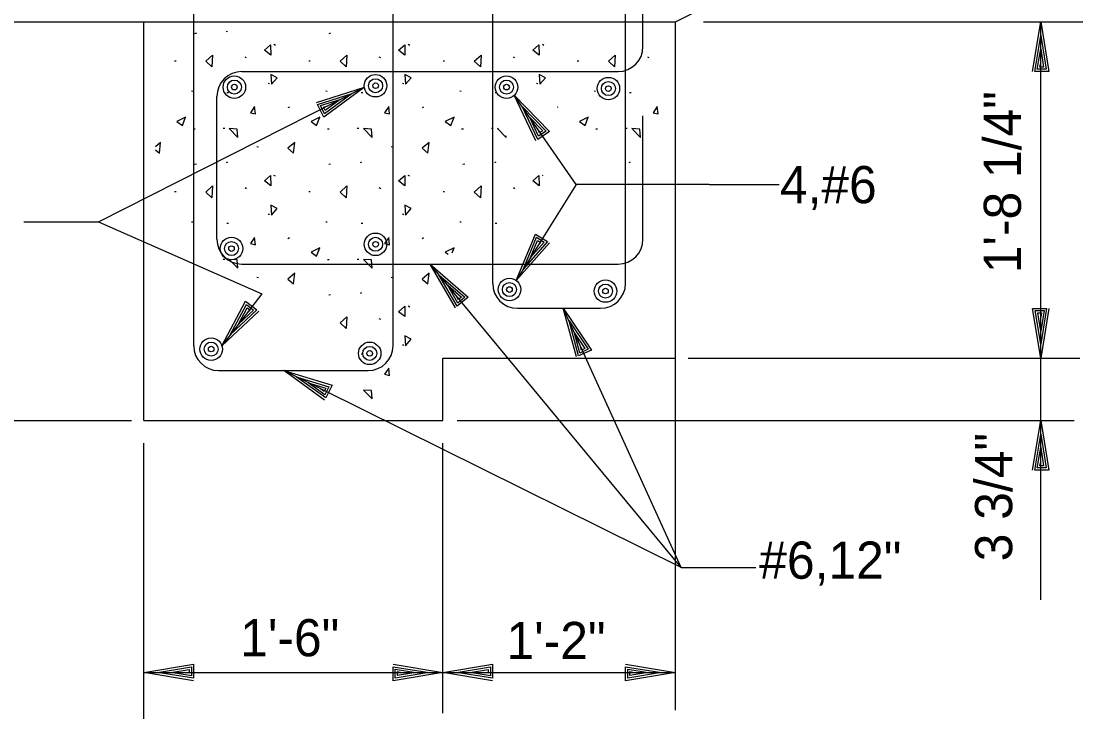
# Model space of a CAD drawing. Extents: x -48 to 108, y -5 to 100.
# Drawn here: x 89 to 99.6, y 26.59 to 33.58 of the extents above; entities that cross this region are included whole.
import ezdxf

# ---------------------------------------------------------------- set-up
doc = ezdxf.new("R2010")
doc.units = 0
for name, color, linetype in [('Level 2', 7, 'Continuous'), ('Level 25', 7, 'Continuous'), ('Level 44', 7, 'Continuous'), ('Level 50', 7, 'Continuous')]:
    doc.layers.add(name, color=color, linetype=linetype)

msp = doc.modelspace()

# ---------------------------------------------------------------- linework, layer by layer
at = {"layer": 'Level 2'}
for p, q in [((95.061, 30.954), (95.061, 36.712)), ((92.728, 30.329), (92.728, 36.585)), ((90.728, 30.329), (90.728, 34.809)), ((93.728, 30.954), (93.728, 34.809)), ((95.236, 33.329), (95.236, 34.852)), ((83.634, 33.579), (95.561, 33.579)), ((90.228, 29.579), (90.228, 33.579)), ((95.561, 30.204), (95.561, 33.579)), ((95.843, 33.579), (99.65, 33.579)), ((99.227, 30.204), (99.227, 33.579)), ((91.211, 33.079), (94.986, 33.079)), ((89.772, 31.573), (92.441, 32.921)), ((90.961, 31.397), (90.961, 32.829)), ((94.567, 31.947), (93.945, 32.842)), ((95.236, 31.397), (95.236, 32.636)), ((94.567, 31.947), (93.962, 30.983)), ((95.901, 31.947), (94.567, 31.947)), ((95.901, 31.947), (96.601, 31.947)), ((89.024, 31.573), (89.772, 31.573)), ((89.772, 31.573), (91.411, 30.849)), ((91.211, 31.147), (94.986, 31.147)), ((95.619, 28.104), (93.1, 31.147)), ((91.411, 30.849), (91.01, 30.329)), ((93.978, 30.704), (94.811, 30.704)), ((95.619, 28.104), (94.436, 30.704)), ((93.228, 29.579), (93.228, 30.204)), ((93.228, 30.204), (95.561, 30.204)), ((95.561, 26.671), (95.561, 30.204)), ((95.688, 30.204), (99.621, 30.204)), ((99.227, 29.579), (99.227, 30.204)), ((90.978, 30.079), (92.478, 30.079)), ((95.619, 28.104), (91.632, 30.079)), ((85.957, 29.579), (90.105, 29.579)), ((90.228, 29.579), (93.228, 29.579)), ((93.371, 29.579), (99.563, 29.579)), ((99.227, 27.779), (99.227, 29.579)), ((90.228, 26.585), (90.228, 29.351)), ((93.228, 26.642), (93.228, 29.351)), ((95.619, 28.104), (96.367, 28.104)), ((90.228, 27.051), (93.228, 27.051)), ((93.228, 27.051), (95.561, 27.051))]:
    msp.add_line(p, q, dxfattribs=at)
for centre, start, end in [((94.986, 33.329), 270, 0), ((91.211, 32.829), 90, 180), ((91.211, 31.397), 180, 270), ((94.986, 31.397), 270, 0), ((93.978, 30.954), 180, 270), ((94.811, 30.954), 270, 0), ((90.978, 30.329), 180, 270), ((92.478, 30.329), 270, 0)]:
    msp.add_arc(centre, 0.25, start, end, dxfattribs=at)
at = {"layer": 'Level 25'}
msp.add_line((95.561, 33.579), (100.142, 35.869), dxfattribs=at)
at = {"layer": 'Level 44'}
for p, q in [((90.755, 33.463), (90.737, 33.458)), ((91.066, 33.481), (91.053, 33.476)), ((92.102, 33.463), (92.084, 33.458)), ((91.548, 33.34), (91.533, 33.349)), ((92.895, 33.34), (92.88, 33.349)), ((94.242, 33.34), (94.227, 33.349)), ((91.258, 33.216), (91.244, 33.222)), ((92.605, 33.216), (92.59, 33.222)), ((93.951, 33.216), (93.937, 33.222)), ((95.298, 33.216), (95.284, 33.222)), ((90.551, 33.184), (90.536, 33.182)), ((91.898, 33.184), (91.883, 33.182)), ((93.244, 33.184), (93.23, 33.182)), ((94.591, 33.184), (94.576, 33.182)), ((90.719, 32.879), (90.706, 32.881)), ((91.488, 32.957), (91.475, 32.958)), ((92.066, 32.879), (92.053, 32.881)), ((92.835, 32.957), (92.822, 32.958)), ((93.413, 32.879), (93.399, 32.881)), ((94.182, 32.957), (94.168, 32.958)), ((94.759, 32.879), (94.746, 32.881)), ((91.078, 32.867), (91.06, 32.867)), ((92.425, 32.867), (92.407, 32.867)), ((93.771, 32.867), (93.753, 32.867)), ((95.118, 32.867), (95.1, 32.867)), ((91.689, 32.722), (91.673, 32.714)), ((93.035, 32.722), (93.019, 32.714)), ((94.382, 32.722), (94.374, 32.718)), ((90.741, 32.5), (90.723, 32.5)), ((91.039, 32.507), (91.022, 32.507)), ((92.087, 32.5), (92.069, 32.5)), ((92.386, 32.507), (92.369, 32.507)), ((93.434, 32.5), (93.416, 32.5)), ((93.733, 32.507), (93.716, 32.507)), ((94.781, 32.5), (94.763, 32.5)), ((95.079, 32.507), (95.062, 32.507)), ((91.379, 32.32), (91.361, 32.323)), ((92.725, 32.32), (92.708, 32.323)), ((90.755, 32.151), (90.737, 32.146)), ((91.066, 32.169), (91.053, 32.164)), ((92.102, 32.151), (92.084, 32.146)), ((92.412, 32.169), (92.399, 32.164)), ((93.448, 32.151), (93.43, 32.146)), ((93.759, 32.169), (93.746, 32.164)), ((95.106, 32.169), (95.093, 32.164)), ((91.548, 32.028), (91.533, 32.037)), ((92.895, 32.028), (92.88, 32.037)), ((94.233, 32.033), (94.227, 32.037)), ((90.551, 31.872), (90.536, 31.871)), ((91.258, 31.904), (91.244, 31.911)), ((91.898, 31.872), (91.883, 31.871)), ((92.605, 31.904), (92.59, 31.911)), ((93.244, 31.872), (93.23, 31.871)), ((93.951, 31.904), (93.937, 31.911)), ((91.488, 31.645), (91.475, 31.646)), ((92.835, 31.645), (92.822, 31.646)), ((90.719, 31.567), (90.706, 31.569)), ((91.078, 31.556), (91.06, 31.556)), ((92.066, 31.567), (92.053, 31.569)), ((92.425, 31.556), (92.407, 31.556)), ((93.413, 31.567), (93.399, 31.569)), ((93.771, 31.556), (93.753, 31.556)), ((91.689, 31.41), (91.673, 31.402)), ((93.035, 31.41), (93.019, 31.402)), ((91.039, 31.195), (91.022, 31.195)), ((92.087, 31.189), (92.069, 31.189)), ((92.386, 31.195), (92.369, 31.195)), ((91.379, 31.009), (91.361, 31.012)), ((92.725, 31.009), (92.708, 31.012)), ((92.412, 30.858), (92.399, 30.853)), ((92.102, 30.84), (92.084, 30.835)), ((92.895, 30.716), (92.88, 30.725)), ((92.605, 30.592), (92.59, 30.599)), ((92.835, 30.333), (92.822, 30.334)), ((92.425, 30.244), (92.407, 30.244))]:
    msp.add_line(p, q, dxfattribs=at)
for points in [[(91.501, 33.245), (91.437, 33.294), (91.498, 33.348)], [(92.848, 33.245), (92.784, 33.294), (92.845, 33.348)], [(94.194, 33.245), (94.13, 33.294), (94.192, 33.348)], [(90.911, 33.125), (90.85, 33.182), (90.918, 33.243)], [(92.258, 33.125), (92.196, 33.182), (92.265, 33.243)], [(93.605, 33.125), (93.543, 33.182), (93.611, 33.243)], [(94.951, 33.125), (94.89, 33.182), (94.958, 33.243)], [(91.508, 32.952), (91.565, 33.016), (91.501, 33.05)], [(92.854, 32.952), (92.911, 33.016), (92.848, 33.05)], [(94.201, 32.952), (94.258, 33.016), (94.194, 33.05)], [(91.347, 32.654), (91.338, 32.727), (91.297, 32.666)], [(92.694, 32.654), (92.685, 32.727), (92.644, 32.666)], [(95.387, 32.654), (95.378, 32.727), (95.337, 32.666)], [(90.615, 32.539), (90.646, 32.621), (90.558, 32.578)], [(91.961, 32.539), (91.993, 32.621), (91.905, 32.578)], [(93.308, 32.539), (93.34, 32.621), (93.251, 32.578)], [(94.655, 32.539), (94.686, 32.621), (94.598, 32.578)], [(91.164, 32.502), (91.084, 32.507), (91.171, 32.418)], [(92.511, 32.502), (92.431, 32.507), (92.518, 32.418)], [(95.204, 32.502), (95.124, 32.507), (95.211, 32.418)], [(91.743, 32.368), (91.674, 32.309), (91.731, 32.261)], [(93.089, 32.368), (93.021, 32.309), (93.078, 32.261)], [(91.501, 31.934), (91.437, 31.982), (91.498, 32.036)], [(92.848, 31.934), (92.784, 31.982), (92.845, 32.036)], [(94.194, 31.934), (94.13, 31.982), (94.192, 32.036)], [(90.911, 31.813), (90.85, 31.87), (90.918, 31.931)], [(92.258, 31.813), (92.196, 31.87), (92.265, 31.931)], [(93.605, 31.813), (93.543, 31.87), (93.611, 31.931)], [(91.508, 31.64), (91.565, 31.704), (91.501, 31.738)], [(92.854, 31.64), (92.911, 31.704), (92.848, 31.738)], [(91.347, 31.342), (91.338, 31.415), (91.297, 31.354)], [(92.694, 31.342), (92.685, 31.415), (92.644, 31.354)], [(91.961, 31.228), (91.993, 31.309), (91.905, 31.266)], [(91.164, 31.191), (91.084, 31.195), (91.171, 31.106)], [(92.511, 31.191), (92.431, 31.195), (92.518, 31.106)], [(91.743, 31.057), (91.674, 30.997), (91.731, 30.949)], [(93.089, 31.057), (93.021, 30.997), (93.078, 30.949)], [(92.848, 30.622), (92.784, 30.67), (92.845, 30.725)], [(92.258, 30.502), (92.196, 30.559), (92.265, 30.62)], [(92.854, 30.329), (92.911, 30.393), (92.848, 30.427)], [(92.694, 30.031), (92.685, 30.104), (92.644, 30.043)], [(92.511, 29.879), (92.431, 29.883), (92.518, 29.795)]]:
    msp.add_lwpolyline(points, close=True, dxfattribs=at)
for points in [[(93.785, 32.506), (93.778, 32.507), (93.864, 32.418), (93.863, 32.433)], [(90.396, 32.368), (90.346, 32.324)], [(90.346, 32.294), (90.384, 32.261), (90.396, 32.368)], [(93.32, 31.26), (93.34, 31.309), (93.251, 31.266), (93.28, 31.247)]]:
    msp.add_lwpolyline(points, dxfattribs=at)
at = {"layer": 'Level 50'}
for p, q in [((99.227, 33.579), (99.227, 33.579)), ((99.227, 33.44), (99.227, 33.44)), ((92.441, 32.921), (92.441, 32.921)), ((92.318, 32.858), (92.318, 32.858)), ((93.945, 32.842), (93.945, 32.842)), ((94.024, 32.728), (94.024, 32.728)), ((93.1, 31.147), (93.1, 31.147)), ((94.036, 31.1), (94.036, 31.1)), ((93.189, 31.04), (93.189, 31.04)), ((93.962, 30.983), (93.962, 30.983)), ((94.436, 30.704), (94.436, 30.704)), ((94.494, 30.578), (94.494, 30.578)), ((91.094, 30.439), (91.094, 30.439)), ((91.01, 30.329), (91.01, 30.329)), ((99.227, 30.343), (99.227, 30.343)), ((99.227, 30.204), (99.227, 30.204)), ((91.632, 30.079), (91.632, 30.079)), ((91.756, 30.017), (91.756, 30.017)), ((99.227, 29.579), (99.227, 29.579)), ((99.227, 29.44), (99.227, 29.44)), ((90.228, 27.051), (90.228, 27.051)), ((90.366, 27.051), (90.366, 27.051)), ((93.089, 27.051), (93.089, 27.051)), ((93.228, 27.051), (93.228, 27.051)), ((93.228, 27.051), (93.228, 27.051)), ((93.366, 27.051), (93.366, 27.051)), ((95.422, 27.051), (95.422, 27.051)), ((95.561, 27.051), (95.561, 27.051))]:
    msp.add_line(p, q, dxfattribs=at)
for points in [[(99.144, 33.08), (99.227, 33.579), (99.309, 33.08), (99.168, 33.08), (99.227, 33.44), (99.283, 33.102), (99.192, 33.102), (99.227, 33.307), (99.256, 33.123), (99.219, 33.123), (99.227, 33.168)], [(91.959, 32.77), (92.441, 32.921), (92.034, 32.622), (91.97, 32.748), (92.318, 32.858), (92.041, 32.656), (92, 32.737), (92.199, 32.798), (92.048, 32.689), (92.031, 32.722), (92.075, 32.736)], [(94.162, 32.385), (93.945, 32.842), (94.298, 32.479), (94.182, 32.399), (94.024, 32.728), (94.264, 32.482), (94.189, 32.43), (94.1, 32.618), (94.23, 32.484), (94.199, 32.463), (94.18, 32.504)], [(94.297, 31.361), (93.962, 30.983), (94.157, 31.449), (94.277, 31.374), (94.036, 31.1), (94.168, 31.417), (94.245, 31.369), (94.107, 31.213), (94.179, 31.385), (94.211, 31.365), (94.18, 31.331)], [(93.355, 30.71), (93.1, 31.147), (93.482, 30.816), (93.373, 30.726), (93.189, 31.04), (93.448, 30.815), (93.378, 30.757), (93.274, 30.938), (93.414, 30.815), (93.385, 30.791), (93.362, 30.831)], [(91.38, 30.674), (91.01, 30.329), (91.249, 30.775), (91.361, 30.688), (91.094, 30.439), (91.257, 30.741), (91.329, 30.686), (91.176, 30.545), (91.265, 30.708), (91.295, 30.686), (91.26, 30.654)], [(94.568, 30.216), (94.436, 30.704), (94.718, 30.284), (94.589, 30.226), (94.494, 30.578), (94.685, 30.293), (94.602, 30.255), (94.549, 30.456), (94.652, 30.301), (94.618, 30.285), (94.606, 30.33)], [(99.309, 30.703), (99.227, 30.204), (99.144, 30.703), (99.285, 30.703), (99.227, 30.343), (99.171, 30.681), (99.261, 30.681), (99.227, 30.476), (99.197, 30.66), (99.235, 30.66), (99.227, 30.615)], [(92.042, 29.783), (91.632, 30.079), (92.116, 29.932), (92.053, 29.805), (91.756, 30.017), (92.085, 29.917), (92.044, 29.836), (91.876, 29.958), (92.054, 29.903), (92.037, 29.869), (92, 29.897)], [(99.144, 29.08), (99.227, 29.579), (99.309, 29.08), (99.168, 29.08), (99.227, 29.44), (99.283, 29.102), (99.192, 29.102), (99.227, 29.307), (99.256, 29.123), (99.219, 29.123), (99.227, 29.168)], [(90.726, 26.968), (90.228, 27.051), (90.726, 27.133), (90.726, 26.992), (90.366, 27.051), (90.705, 27.107), (90.705, 27.016), (90.5, 27.051), (90.684, 27.08), (90.684, 27.043), (90.638, 27.051)], [(92.729, 27.133), (93.228, 27.051), (92.729, 26.968), (92.729, 27.109), (93.089, 27.051), (92.75, 26.995), (92.75, 27.085), (92.956, 27.051), (92.772, 27.021), (92.772, 27.059), (92.817, 27.051)], [(93.726, 26.968), (93.228, 27.051), (93.726, 27.133), (93.726, 26.992), (93.366, 27.051), (93.705, 27.107), (93.705, 27.016), (93.5, 27.051), (93.684, 27.08), (93.684, 27.043), (93.638, 27.051)], [(95.062, 27.133), (95.561, 27.051), (95.062, 26.968), (95.062, 27.109), (95.422, 27.051), (95.084, 26.995), (95.084, 27.085), (95.289, 27.051), (95.105, 27.021), (95.105, 27.059), (95.15, 27.051)]]:
    msp.add_lwpolyline(points, dxfattribs=at)
for centre, radius in [((91.136, 32.923), 0.113), ((91.136, 32.923), 0.0703), ((92.553, 32.937), 0.113), ((92.553, 32.937), 0.0703), ((93.867, 32.923), 0.113), ((93.867, 32.923), 0.0703), ((94.889, 32.908), 0.113), ((94.889, 32.908), 0.0703), ((91.136, 32.923), 0.0281), ((92.553, 32.937), 0.0281), ((93.867, 32.923), 0.0281), ((94.889, 32.908), 0.0281), ((91.107, 31.303), 0.113), ((92.553, 31.346), 0.113), ((92.553, 31.346), 0.0703), ((91.107, 31.303), 0.0703), ((91.107, 31.303), 0.0281), ((92.553, 31.346), 0.0281), ((93.896, 30.892), 0.113), ((94.86, 30.877), 0.113), ((93.896, 30.892), 0.0703), ((93.896, 30.892), 0.0281), ((94.86, 30.877), 0.0703), ((94.86, 30.877), 0.0281), ((90.903, 30.295), 0.113), ((90.903, 30.295), 0.0703), ((92.494, 30.252), 0.113), ((90.903, 30.295), 0.0281), ((92.494, 30.252), 0.0703), ((92.494, 30.252), 0.0281)]:
    msp.add_circle(centre, radius, dxfattribs=at)

# ---------------------------------------------------------------- texts
at = {"layer": 'Level 25'}
for s, p in [('1\'-8 1/4"', (99.029, 31.056)), ('3 3/4"', (98.941, 28.166))]:
    msp.add_text(s, height=0.3733, rotation=90, dxfattribs=at).set_placement(p)
for s, p in [('4,#6', (96.61, 31.758)), ('#6,12"', (96.403, 27.991)), ('1\'-6"', (91.195, 27.213)), ('1\'-2"', (93.867, 27.185))]:
    msp.add_text(s, height=0.3733, dxfattribs=at).set_placement(p)

doc.saveas('drawing.dxf')
